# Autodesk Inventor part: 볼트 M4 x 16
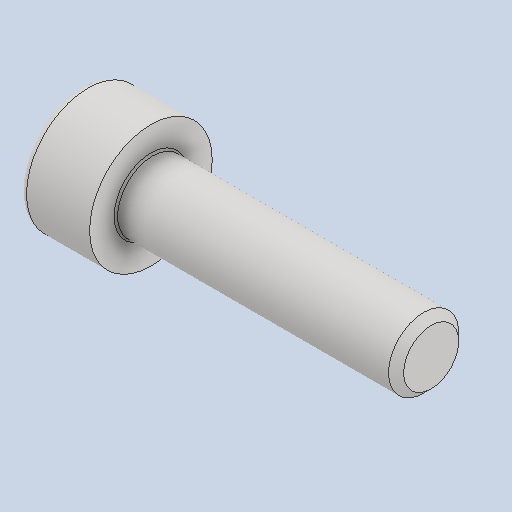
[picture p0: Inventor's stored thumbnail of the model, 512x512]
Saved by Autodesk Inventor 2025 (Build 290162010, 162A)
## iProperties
Created: 2024-07
Part Number: 볼트 M4 x 16
Material: 스테인리스강
Description: 6각 소켓 머리 캡 나사
Document SubType Name: Modeling
Designer: Admin
Density: 8.08 g/cm^3
Appearance: 기본값
Author: jhkim
Sending System: Autodesk Inventor 2025
Preprocessor: ST-DEVELOPER v20
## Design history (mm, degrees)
feature "Solid1"
node "솔리드1"
